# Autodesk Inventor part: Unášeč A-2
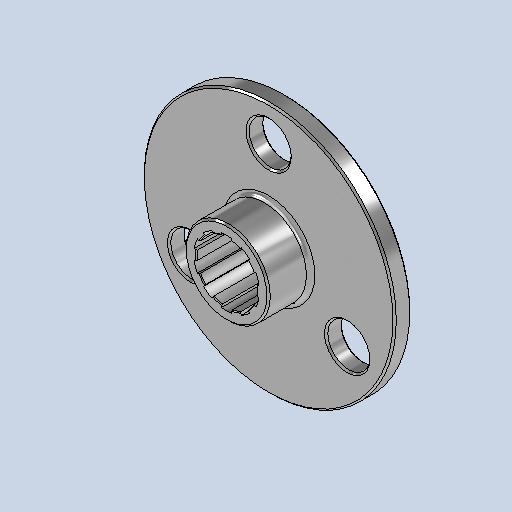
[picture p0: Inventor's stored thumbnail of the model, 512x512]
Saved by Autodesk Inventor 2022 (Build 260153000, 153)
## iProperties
Created: 2025-05
Part Number: Unášeč A-2
Material: Všeobecné
Document SubType Name: Modeling
Designer: jbart
Density: 1 g/cm^3
Appearance: Broušená
Mass: 1373.6 g
Surface Area: 1803.2 cm^2
Volume: 1373.6 cm^3
Author: jbart
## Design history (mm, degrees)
sketch "Náčrt1"
  geometry: L1 (0, 108)-(93.531, -54); L2 (93.531, -54)-(-93.531, -54); L3 (-93.531, -54)-(0, 108); L4 (0, 108)-(0, 0); L5 (0, 0)-(93.531, -54); L6 (0, 0)-(-93.531, -54); C1 r 150 at (0, 0); C2 r 25 at (0, 108); C3 r 25 at (-93.531, -54); C4 r 25 at (93.531, -54); 1 further point
  constraints: 12 end point, 5 coincident, 4 centre point, 1 vertical, 7 other
  dimensions: "d0" = 108 distance of L4.end L1.end; "d1" = 300 diameter of C1; "d2" = 50 diameter of C2; "d3" = 50 diameter of C3; "d4" = 50 diameter of C4
extrude "Vysunutí1" new body sketch "Náčrt1" distance "d5" = 20; taper "d6" = 0 deg
sketch "Náčrt2"
  geometry: C1 r 50 at (0, 0); 1 further point
  constraints: 1 centre point, 1 coincident
  dimensions: "d7" = 100 diameter of C1
extrude "Vysunutí2" join sketch "Náčrt2" distance "d8" = 50; taper "d9" = 0 deg
sketch "Náčrt3"
  geometry: C1 r 36 at (0, 0); 1 further point
  constraints: 1 centre point, 1 coincident
  dimensions: "d10" = 72 diameter of C1
extrude "Vysunutí3" cut sketch "Náčrt3" extent not by distance; stored distance "d11" = 0; taper "d12" = 0 deg
sketch "Náčrt4"
  geometry: L1 (-6, 38.536)-(-6, 35.496); L2 (6, 38.536)-(6, 35.496); L3 (0, 0)-(0, 5); A1 r 36 centre (0, 0) between (-6, 35.496) and (6, 35.496) reference; A2 r 39 centre (0, 0) between (6, 38.536) and (-6, 38.536); 1 further point
  constraints: 6 end point, 4 point on circle, 3 vertical, 1 centre point, 1 coincident, 1 other
  dimensions: "d13" = 78 diameter of A2; "d14" = 12 distance between parallel lines of L2 L1; "d15" = 5 distance of L3.start L3.end
extrude "Vysunutí4" cut sketch "Náčrt4" extent not by distance; stored distance "d16" = 0; taper "d17" = 0 deg
pattern_circular "Kruhové pole1" dims angle "d19" = 360 deg
fillet "Zaoblení1" dims "d21" = 5
chamfer "Zkosení1" distance "d22" = 2; stored, may be unused: second distance "d23" = 2, angle "d24" = 45 deg
chamfer "Zkosení2" distance "d25" = 1; stored, may be unused: second distance "d26" = 2, angle "d27" = 45 deg
node "Těleso1"
